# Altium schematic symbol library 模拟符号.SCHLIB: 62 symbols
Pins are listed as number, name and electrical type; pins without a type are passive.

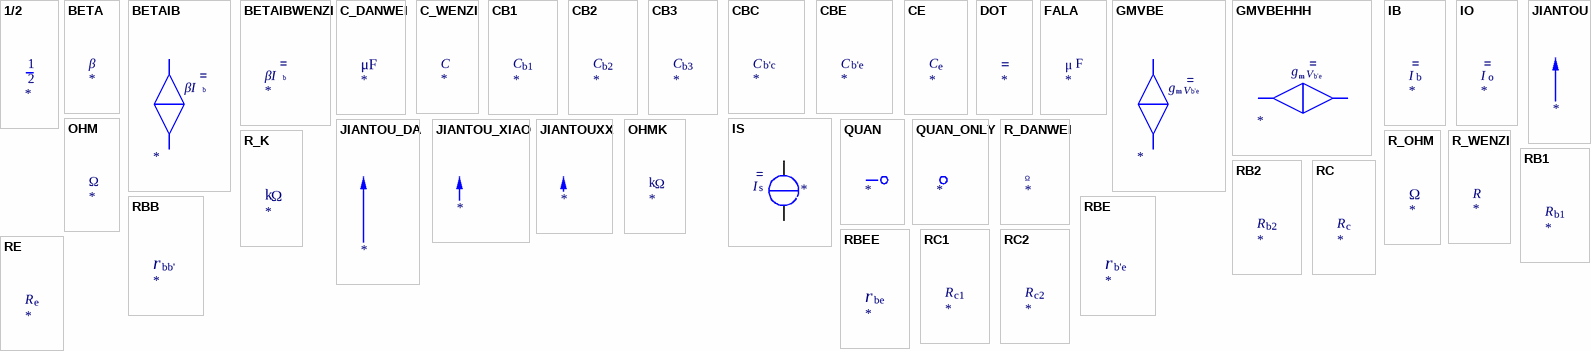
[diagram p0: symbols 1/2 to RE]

## 1/2
designator ?

## BETA
designator ?

## BETAIB
designator ?

## BETAIBWENZI
designator ?

## C_DANWEI
designator ?

## C_WENZI
designator ?

## CB1
designator ?

## CB2
designator ?

## CB3
designator ?

## CBC
designator ?

## CBE
designator ?

## CE
designator ?

## DOT
designator ?

## FALA
designator ?

## GMVBE
designator ?

## GMVBEHHH
designator ?

## IB
designator ?

## IO
designator ?

## IS
designator ?
pins: 1, 2

## JIANTOU
designator ?

## JIANTOU_DA
designator ?

## JIANTOU_XIAO
designator ?

## JIANTOUXX
designator ?

## OHM
designator ?

## OHMK
designator ?

## QUAN
designator ?

## QUAN_ONLY
designator ?

## R_DANWEI
designator ?

## R_K
designator ?

## R_OHM
designator ?

## R_WENZI
designator ?

## RB1
designator ?

## RB2
designator ?

## RBB
designator ?

## RBE
designator ?

## RBEE
designator ?

## RC
designator ?

## RC1
designator ?

## RC2
designator ?

## RE
designator ?

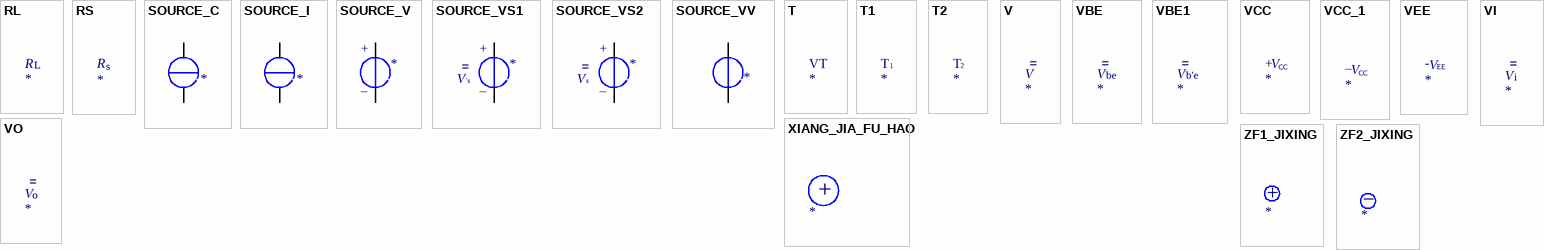
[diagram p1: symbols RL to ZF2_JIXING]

## RL
designator ?

## RS
designator ?

## SOURCE_C
designator ?
pins: 1, 2

## SOURCE_I
designator ?
pins: 1, 2

## SOURCE_V
designator ?
pins: 1, 2

## SOURCE_VS1
designator ?
pins: 1, 2

## SOURCE_VS2
designator ?
pins: 1, 2

## SOURCE_VV
designator ?
pins: 1, 2

## T
designator ?

## T1
designator ?

## T2
designator ?

## V
designator ?

## VBE
designator ?

## VBE1
designator ?

## VCC
designator ?

## VCC_1
designator ?

## VEE
designator ?

## VI
designator ?

## VO
designator ?

## XIANG_JIA_FU_HAO
designator ?

## ZF1_JIXING
designator ?

## ZF2_JIXING
designator ?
